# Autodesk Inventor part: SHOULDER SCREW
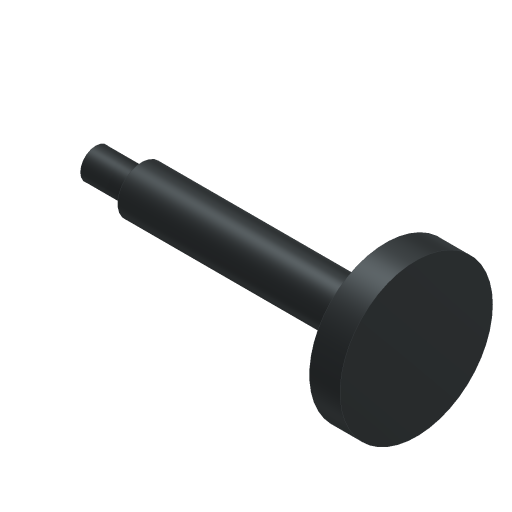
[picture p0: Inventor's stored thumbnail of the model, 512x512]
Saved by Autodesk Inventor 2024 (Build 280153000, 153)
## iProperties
Created: 2016-05
Part Number: SHOULDER SCREW
Material: Iron, Cast
Document SubType Name: Modeling
Designer: CADCIM
Density: 7.15 g/cm^3
Appearance: Iron Gray
Mass: 16.5435 g
Surface Area: 15.8336 cm^2
Volume: 2.31378 cm^3
Author: CADCIM
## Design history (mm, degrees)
revolve "Revolution1" stored, may be unused: angle "d6" = 90 deg
body "Solid1"
sketch "Sketch1"
  geometry: L1 (0, 0)-(0, 2); L2 (0, 2)-(6, 2); L3 (6, 2)-(6, 3.125); L4 (6, 3.125)-(38, 3.125); L5 (38, 3.125)-(38, 10); L6 (38, 10)-(42, 10); L7 (42, 10)-(42, 0); L8 (42, 0)-(0, 0)
  constraints: 16 end point, 7 perpendicular, 1 vertical
  dimensions: "d0" = 4 diameter of L2 L8; "d1" = 6.25 diameter of L4 L8; "d2" = 20 diameter of L6 L8; "d3" = 32 distance between parallel lines of L5 L3; "d4" = 42 distance between parallel lines of L1 L7; "d5" = 4 distance of L5.end L6.end
